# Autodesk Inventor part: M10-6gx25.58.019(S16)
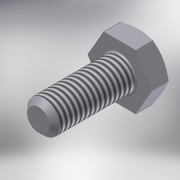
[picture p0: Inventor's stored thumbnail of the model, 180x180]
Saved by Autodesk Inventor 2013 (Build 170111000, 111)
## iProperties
Shininess: 20.0
Length Units: 11269
Angle Units: 11279
Time Units: 11290
Mass Units: 11283
Length Display Precision: 3
Angle Display Precision: 2
Created: 2001-10
Document SubType Name: Modeling
Designer: SOleg
Material: Steel, Mild
Description: Болт М10-6gx25.58.019 (S16) ГОСТ 7798-70
Density: 7.86 g/cm^3
Density: 0.0
Volumn: 0.0
Area: 0.0
PropertySet Name: Model Information
Control State: 0
Master: False
Checked Out: True
Last Check In Date: 2008-10-15
Checked Out Date: 2008-10-15
Author: SOleg
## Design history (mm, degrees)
sketch "Sketch1"
  geometry: L1 (484.39, 469.325)-(474.575, 469.325); L2 (489.297, 460.825)-(484.39, 469.325); L3 (484.39, 452.325)-(489.297, 460.825); L4 (474.575, 452.325)-(484.39, 452.325); L5 (469.667, 460.825)-(474.575, 452.325); L6 (474.575, 469.325)-(469.667, 460.825); C1 r 8.5 at (479.482, 460.825)
  constraints: 12 end point, 6 tangent, 3 parallel, 1 centre point, 1 horizontal, 1 other
  dimensions: "d1" = 120 deg angle of L1 L2; "d3" = 120 deg angle of L5 L6; "d5" = 17 diameter of C1
extrude "ExtrusionBlind1" new body sketch "Sketch1" distance "d6" = 6.4; taper "d7" = 0 deg
sketch "Sketch2"
  geometry: C1 r 7.8 at (479.482, -460.825)
  constraints: 1 centre point
  dimensions: "d12" = 15.6 diameter of C1
extrude "ExtrusionThru1" sketch "Sketch2" stored distance "d13" = 0.13; taper "d14" = 60 deg
sketch "Sketch3"
  geometry: L1 (469.667, 460.825)-(470.167, 461.691); L2 (474.575, 469.325)-(475.575, 469.325); L3 (484.39, 469.325)-(484.89, 468.459); C1 r 5 at (479.482, 460.825); C2 r 8.5 at (479.482, 460.825)
  constraints: 6 end point, 3 tangent, 2 centre point, 1 coincident
  dimensions: "d16" = 10 diameter of C1
extrude "ExtrusionBlind2" join sketch "Sketch3" distance "d17" = 25; taper "d18" = 0 deg
fillet "Fillet1" dims "d19" = 0.5
chamfer "Chamfer1" distance "d20" = 1.6; stored, may be unused: second distance "d21" = 1.6, angle "d24" = 45 deg
thread "Thread1" dims "d22" = 10, "d23" = 0
body "Solid1"
other parameters: "d0" = 120 deg (derived), "d2" = 120 deg (derived), "d4" = 17 (derived), "d8" = 0, "d9" = 0, "d10" = 0, "d11" = 15.6 (derived)
